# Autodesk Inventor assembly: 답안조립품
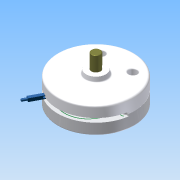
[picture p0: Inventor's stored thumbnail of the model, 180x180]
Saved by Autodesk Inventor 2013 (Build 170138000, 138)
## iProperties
Created: 2015-06
Part Number: 답안조립품
Document SubType Name: Assembly
Designer: Administrator
Author: Administrator
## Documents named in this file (9)
- C:\Documents and Settings\Administrator\바탕 화면\450631V1005\답안조립품.iam
- C:\Documents and Settings\Administrator\바탕 화면\450631V1005\본체.ipt
- C:\Documents and Settings\Administrator\바탕 화면\450631V1005\덮개.ipt
- C:\Documents and Settings\Administrator\바탕 화면\450631V1005\축.ipt
- C:\Documents and Settings\Administrator\바탕 화면\450631V1005\슬라이더2.ipt
- C:\Documents and Settings\Administrator\바탕 화면\450631V1005\베어링62_22.ipt
- C:\Documents and Settings\Administrator\바탕 화면\450631V1005\멈춤링.ipt
- C:\Documents and Settings\Administrator\바탕 화면\450631V1005\슬라이더.ipt
- C:\Documents and Settings\Administrator\바탕 화면\450631V1005\평행핀.ipt
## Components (5 placed, 3 different names)
1. KS B 2023 62/22 - 22 x 50 x 14:1
2. KS B 2023 62/22 - 22 x 50 x 14:2
3. KS B 1336 22 x 1.2:1
4. KS B 1336 22 x 1.2:2
5. KS B 1320 B B 5 x  20:1
